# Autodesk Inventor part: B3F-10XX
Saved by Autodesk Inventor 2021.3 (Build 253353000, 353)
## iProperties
Created: 2021-12
Part Number: B3F-10XX
Material: Generic
Document SubType Name: Modeling
Designer: Administrator
Density: 1 g/cm^3
Appearance: Default
Title: B3F-10XX
Author: Administrator
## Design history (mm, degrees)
feature "Body1"
body "Solid1"
